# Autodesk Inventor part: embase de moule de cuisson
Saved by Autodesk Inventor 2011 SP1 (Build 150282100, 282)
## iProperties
Created: 2010-12
Part Number: embase de moule de cuisson
Document SubType Name: Modeling
Designer: eric
Density: 1 g/cm^3
Author: eric
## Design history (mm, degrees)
feature "Base1"
node "Solide1"
node "Corps solides"
node "Corps surfaciques"
